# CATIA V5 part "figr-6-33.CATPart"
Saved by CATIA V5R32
Part number: Part1
Bounding box of the stored display mesh (mm): x -61 to 61, y 0 to 173.636, z 0 to 130.49
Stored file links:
  D:\PROJECTS\Project 2022\CATIA V5 6R 2022\Resources\Part Files\c06_catia_v5_6r2022_prt\figr-6-33.CATPart
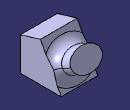
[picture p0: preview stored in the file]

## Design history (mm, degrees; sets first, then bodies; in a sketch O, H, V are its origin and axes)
Body1 (main body)
  Sketch1 on yz-plane, origin (0, 0, 0), H (0, 1, 0), V (0, 0, 1)
    line L1 (0, 0) -> (0, 110.5903)
    line L2 (0, 110.5903) -> (66.2814, 130.4899)
    line L3 (66.2814, 130.4899) -> (135.1646, 0)
    point P3 (135.1646, 0)
    line L4 (135.1646, 0) -> (0, 0)
    vertical: L1 V
    coincidence: P3 H
    horizontal: L4 H
  Pad1: profile Sketch1, direction (1, 0, 0), length 61, mirrored extent
  Sketch2 on face of Pad1, origin (0, 105.7081, 55.8014), H (-1, 0, 0), V (0, -0.4668, 0.8843)
    point P1 (0, 4.9672)
    ellipse A1 centre (0, 4.9672) semi-axes 50.9663, 34.9201 rotation 0
    coincidence: P1 V
  Pad2: profile Sketch2, direction (0, 0.8843, 0.4668), length 61
  Fillet1: radius 29, on edge [face of Pad1 | face of Pad2]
